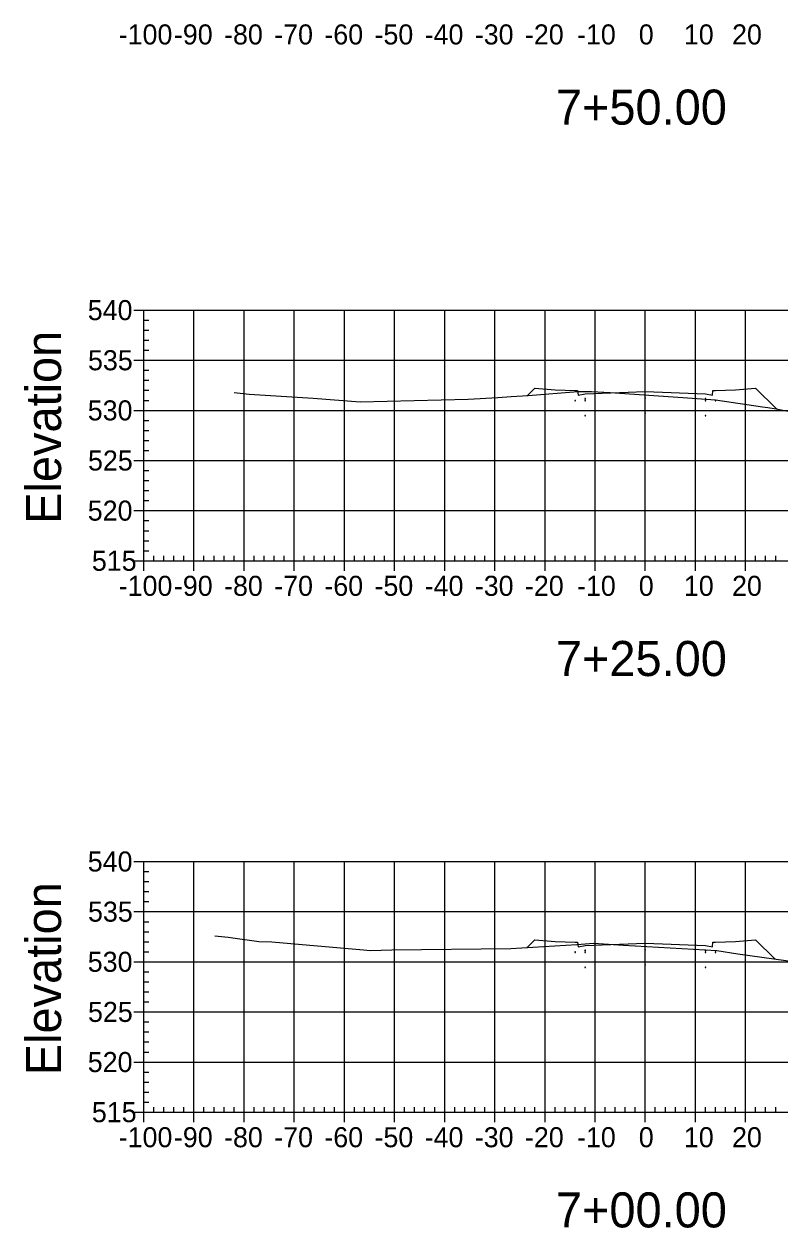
# Model space of a CAD drawing. Extents: x 708103 to 717568, y 374476 to 378707.
# Drawn here: x 716232.6 to 716383.3, y 376985 to 377225.1 of the extents above; entities that cross this region are included whole.
import ezdxf

# ---------------------------------------------------------------- set-up
doc = ezdxf.new("R2010")
doc.units = 0
for name, color, linetype in [('1', 7, 'Continuous'), ('14', 7, 'Continuous'), ('22', 7, 'Continuous'), ('57', 7, 'Continuous'), ('60', 7, 'Continuous'), ('Existing', 7, 'Continuous')]:
    doc.layers.add(name, color=color, linetype=linetype)

msp = doc.modelspace()

# ---------------------------------------------------------------- linework, layer by layer
for points in [[(716356.45, 377150.45), (716356.55, 377150.45), (716356.55, 377150.55), (716356.45, 377150.55)], [(716342.45, 377149.97), (716342.55, 377149.97), (716342.55, 377150.07), (716342.45, 377150.07)], [(716344.45, 377150.31), (716344.55, 377150.31), (716344.55, 377150.41), (716344.45, 377150.41)], [(716344.45, 377149.97), (716344.55, 377149.97), (716344.55, 377150.07), (716344.45, 377150.07)], [(716368.45, 377150.31), (716368.55, 377150.31), (716368.55, 377150.41), (716368.45, 377150.41)], [(716368.45, 377149.97), (716368.55, 377149.97), (716368.55, 377150.07), (716368.45, 377150.07)], [(716370.45, 377149.97), (716370.55, 377149.97), (716370.55, 377150.07), (716370.45, 377150.07)], [(716344.45, 377146.97), (716344.55, 377146.97), (716344.55, 377147.07), (716344.45, 377147.07)], [(716356.45, 377147.45), (716356.55, 377147.45), (716356.55, 377147.55), (716356.45, 377147.55)], [(716368.45, 377146.97), (716368.55, 377146.97), (716368.55, 377147.07), (716368.45, 377147.07)], [(716342.45, 377039.92), (716342.55, 377039.92), (716342.55, 377040.02), (716342.45, 377040.02)], [(716344.45, 377040.26), (716344.55, 377040.26), (716344.55, 377040.36), (716344.45, 377040.36)], [(716344.45, 377039.92), (716344.55, 377039.92), (716344.55, 377040.02), (716344.45, 377040.02)], [(716356.45, 377040.4), (716356.55, 377040.4), (716356.55, 377040.5), (716356.45, 377040.5)], [(716368.45, 377040.26), (716368.55, 377040.26), (716368.55, 377040.36), (716368.45, 377040.36)], [(716368.45, 377039.92), (716368.55, 377039.92), (716368.55, 377040.02), (716368.45, 377040.02)], [(716370.45, 377039.92), (716370.55, 377039.92), (716370.55, 377040.02), (716370.45, 377040.02)], [(716344.45, 377036.92), (716344.55, 377036.92), (716344.55, 377037.02), (716344.45, 377037.02)], [(716356.45, 377037.4), (716356.55, 377037.4), (716356.55, 377037.5), (716356.45, 377037.5)], [(716368.45, 377036.92), (716368.55, 377036.92), (716368.55, 377037.02), (716368.45, 377037.02)]]:
    msp.add_lwpolyline(points, close=True)
at = {"layer": '14'}
for points in [[(716333.03, 377151.03), (716333.03, 377151.08), (716333.03, 377151.03), (716332.98, 377151.03), (716333.03, 377151.03), (716333.03, 377150.98), (716333.03, 377151.03), (716333.08, 377151.03)], [(716382.63, 377148.37), (716382.63, 377148.42), (716382.63, 377148.37), (716382.58, 377148.37), (716382.63, 377148.37), (716382.63, 377148.32), (716382.63, 377148.37), (716382.68, 377148.37)], [(716332.95, 377040.9), (716332.95, 377040.95), (716332.95, 377040.9), (716332.9, 377040.9), (716332.95, 377040.9), (716332.95, 377040.85), (716332.95, 377040.9), (716333, 377040.9)], [(716382.31, 377038.64), (716382.31, 377038.69), (716382.31, 377038.64), (716382.26, 377038.64), (716382.31, 377038.64), (716382.31, 377038.59), (716382.31, 377038.64), (716382.36, 377038.64)]]:
    msp.add_lwpolyline(points, dxfattribs=at)
at = {"layer": '22'}
for points in [[(716333.03, 377151.03), (716334.5, 377152.5), (716338.5, 377152.18), (716342.5, 377152.02), (716343, 377152.02), (716343.08, 377151.11), (716344.5, 377151.36), (716356.5, 377151.84), (716368.5, 377151.36), (716369.91, 377151.11), (716370, 377152.02), (716370.5, 377152.02), (716374.5, 377152.18), (716378.5, 377152.5), (716382.63, 377148.37)], [(716332.95, 377040.9), (716334.5, 377042.45), (716338.5, 377042.13), (716342.5, 377041.97), (716343, 377041.97), (716343.08, 377041.06), (716344.5, 377041.31), (716356.5, 377041.79), (716368.5, 377041.31), (716369.91, 377041.06), (716370, 377041.97), (716370.5, 377041.97), (716374.5, 377042.13), (716378.5, 377042.45), (716382.31, 377038.64)]]:
    msp.add_lwpolyline(points, dxfattribs=at)
at = {"layer": '57'}
for p, q in [((716254.5, 377168.07), (716256.5, 377168.07)), ((716256.5, 377168.07), (716456.5, 377168.07)), ((716256.5, 377118.07), (716256.5, 377168.07)), ((716256.5, 377118.07), (716256.5, 377168.07)), ((716266.5, 377118.07), (716266.5, 377168.07)), ((716276.5, 377118.07), (716276.5, 377168.07)), ((716286.5, 377118.07), (716286.5, 377168.07)), ((716296.5, 377118.07), (716296.5, 377168.07)), ((716306.5, 377118.07), (716306.5, 377168.07)), ((716316.5, 377118.07), (716316.5, 377168.07)), ((716326.5, 377118.07), (716326.5, 377168.07)), ((716336.5, 377118.07), (716336.5, 377168.07)), ((716346.5, 377118.07), (716346.5, 377168.07)), ((716356.5, 377118.07), (716356.5, 377168.07)), ((716366.5, 377118.07), (716366.5, 377168.07)), ((716376.5, 377118.07), (716376.5, 377168.07)), ((716256.5, 377166.07), (716257.5, 377166.07)), ((716256.5, 377164.07), (716257.5, 377164.07)), ((716256.5, 377162.07), (716257.5, 377162.07)), ((716256.5, 377160.07), (716257.5, 377160.07)), ((716254.5, 377158.07), (716256.5, 377158.07)), ((716256.5, 377158.07), (716456.5, 377158.07)), ((716256.5, 377156.07), (716257.5, 377156.07)), ((716256.5, 377154.07), (716257.5, 377154.07)), ((716256.5, 377152.07), (716257.5, 377152.07)), ((716254.5, 377148.07), (716256.5, 377148.07)), ((716256.5, 377150.07), (716257.5, 377150.07)), ((716256.5, 377148.07), (716456.5, 377148.07)), ((716256.5, 377146.07), (716257.5, 377146.07)), ((716256.5, 377144.07), (716257.5, 377144.07)), ((716256.5, 377142.07), (716257.5, 377142.07)), ((716256.5, 377140.07), (716257.5, 377140.07)), ((716254.5, 377138.07), (716256.5, 377138.07)), ((716256.5, 377138.07), (716456.5, 377138.07)), ((716256.5, 377136.07), (716257.5, 377136.07)), ((716256.5, 377134.07), (716257.5, 377134.07)), ((716256.5, 377132.07), (716257.5, 377132.07)), ((716256.5, 377130.07), (716257.5, 377130.07)), ((716254.5, 377128.07), (716256.5, 377128.07)), ((716256.5, 377128.07), (716456.5, 377128.07)), ((716256.5, 377126.07), (716257.5, 377126.07)), ((716256.5, 377124.07), (716257.5, 377124.07)), ((716256.5, 377122.07), (716257.5, 377122.07)), ((716256.5, 377120.07), (716257.5, 377120.07)), ((716254.5, 377118.07), (716256.5, 377118.07)), ((716256.5, 377118.07), (716456.5, 377118.07)), ((716256.5, 377118.07), (716456.5, 377118.07)), ((716256.5, 377116.07), (716256.5, 377118.07)), ((716258.5, 377118.07), (716258.5, 377119.07)), ((716260.5, 377118.07), (716260.5, 377119.07)), ((716262.5, 377118.07), (716262.5, 377119.07)), ((716264.5, 377118.07), (716264.5, 377119.07)), ((716266.5, 377116.07), (716266.5, 377118.07)), ((716268.5, 377118.07), (716268.5, 377119.07)), ((716270.5, 377118.07), (716270.5, 377119.07)), ((716272.5, 377118.07), (716272.5, 377119.07)), ((716274.5, 377118.07), (716274.5, 377119.07)), ((716276.5, 377116.07), (716276.5, 377118.07)), ((716278.5, 377118.07), (716278.5, 377119.07)), ((716280.5, 377118.07), (716280.5, 377119.07)), ((716282.5, 377118.07), (716282.5, 377119.07)), ((716284.5, 377118.07), (716284.5, 377119.07)), ((716286.5, 377116.07), (716286.5, 377118.07)), ((716288.5, 377118.07), (716288.5, 377119.07)), ((716290.5, 377118.07), (716290.5, 377119.07)), ((716292.5, 377118.07), (716292.5, 377119.07)), ((716294.5, 377118.07), (716294.5, 377119.07)), ((716296.5, 377116.07), (716296.5, 377118.07)), ((716298.5, 377118.07), (716298.5, 377119.07)), ((716300.5, 377118.07), (716300.5, 377119.07)), ((716302.5, 377118.07), (716302.5, 377119.07)), ((716304.5, 377118.07), (716304.5, 377119.07)), ((716306.5, 377116.07), (716306.5, 377118.07)), ((716308.5, 377118.07), (716308.5, 377119.07)), ((716310.5, 377118.07), (716310.5, 377119.07)), ((716312.5, 377118.07), (716312.5, 377119.07)), ((716314.5, 377118.07), (716314.5, 377119.07)), ((716316.5, 377116.07), (716316.5, 377118.07)), ((716318.5, 377118.07), (716318.5, 377119.07)), ((716320.5, 377118.07), (716320.5, 377119.07)), ((716322.5, 377118.07), (716322.5, 377119.07)), ((716324.5, 377118.07), (716324.5, 377119.07)), ((716326.5, 377116.07), (716326.5, 377118.07)), ((716328.5, 377118.07), (716328.5, 377119.07)), ((716330.5, 377118.07), (716330.5, 377119.07)), ((716332.5, 377118.07), (716332.5, 377119.07)), ((716334.5, 377118.07), (716334.5, 377119.07)), ((716336.5, 377116.07), (716336.5, 377118.07)), ((716338.5, 377118.07), (716338.5, 377119.07)), ((716340.5, 377118.07), (716340.5, 377119.07)), ((716342.5, 377118.07), (716342.5, 377119.07)), ((716344.5, 377118.07), (716344.5, 377119.07)), ((716346.5, 377116.07), (716346.5, 377118.07)), ((716348.5, 377118.07), (716348.5, 377119.07)), ((716350.5, 377118.07), (716350.5, 377119.07)), ((716352.5, 377118.07), (716352.5, 377119.07)), ((716354.5, 377118.07), (716354.5, 377119.07)), ((716356.5, 377116.07), (716356.5, 377118.07)), ((716358.5, 377118.07), (716358.5, 377119.07)), ((716360.5, 377118.07), (716360.5, 377119.07)), ((716362.5, 377118.07), (716362.5, 377119.07)), ((716364.5, 377118.07), (716364.5, 377119.07)), ((716366.5, 377116.07), (716366.5, 377118.07)), ((716368.5, 377118.07), (716368.5, 377119.07)), ((716370.5, 377118.07), (716370.5, 377119.07)), ((716372.5, 377118.07), (716372.5, 377119.07)), ((716374.5, 377118.07), (716374.5, 377119.07)), ((716376.5, 377116.07), (716376.5, 377118.07)), ((716378.5, 377118.07), (716378.5, 377119.07)), ((716380.5, 377118.07), (716380.5, 377119.07)), ((716382.5, 377118.07), (716382.5, 377119.07)), ((716254.5, 377058.07), (716256.5, 377058.07)), ((716256.5, 377058.07), (716456.5, 377058.07)), ((716256.5, 377008.07), (716256.5, 377058.07)), ((716256.5, 377008.07), (716256.5, 377058.07)), ((716266.5, 377008.07), (716266.5, 377058.07)), ((716276.5, 377008.07), (716276.5, 377058.07)), ((716286.5, 377008.07), (716286.5, 377058.07)), ((716296.5, 377008.07), (716296.5, 377058.07)), ((716306.5, 377008.07), (716306.5, 377058.07)), ((716316.5, 377008.07), (716316.5, 377058.07)), ((716326.5, 377008.07), (716326.5, 377058.07)), ((716336.5, 377008.07), (716336.5, 377058.07)), ((716346.5, 377008.07), (716346.5, 377058.07)), ((716356.5, 377008.07), (716356.5, 377058.07)), ((716366.5, 377008.07), (716366.5, 377058.07)), ((716376.5, 377008.07), (716376.5, 377058.07)), ((716256.5, 377056.07), (716257.5, 377056.07)), ((716256.5, 377054.07), (716257.5, 377054.07)), ((716256.5, 377052.07), (716257.5, 377052.07)), ((716256.5, 377050.07), (716257.5, 377050.07)), ((716254.5, 377048.07), (716256.5, 377048.07)), ((716256.5, 377048.07), (716456.5, 377048.07)), ((716256.5, 377046.07), (716257.5, 377046.07)), ((716256.5, 377044.07), (716257.5, 377044.07)), ((716256.5, 377042.07), (716257.5, 377042.07)), ((716256.5, 377040.07), (716257.5, 377040.07)), ((716254.5, 377038.07), (716256.5, 377038.07)), ((716256.5, 377038.07), (716456.5, 377038.07)), ((716256.5, 377036.07), (716257.5, 377036.07)), ((716256.5, 377034.07), (716257.5, 377034.07)), ((716256.5, 377032.07), (716257.5, 377032.07)), ((716254.5, 377028.07), (716256.5, 377028.07)), ((716256.5, 377030.07), (716257.5, 377030.07)), ((716256.5, 377028.07), (716456.5, 377028.07)), ((716256.5, 377026.07), (716257.5, 377026.07)), ((716256.5, 377024.07), (716257.5, 377024.07)), ((716256.5, 377022.07), (716257.5, 377022.07)), ((716256.5, 377020.07), (716257.5, 377020.07)), ((716254.5, 377018.07), (716256.5, 377018.07)), ((716256.5, 377018.07), (716456.5, 377018.07)), ((716256.5, 377016.07), (716257.5, 377016.07)), ((716256.5, 377014.07), (716257.5, 377014.07)), ((716256.5, 377012.07), (716257.5, 377012.07)), ((716256.5, 377010.07), (716257.5, 377010.07)), ((716258.5, 377008.07), (716258.5, 377009.07)), ((716260.5, 377008.07), (716260.5, 377009.07)), ((716262.5, 377008.07), (716262.5, 377009.07)), ((716264.5, 377008.07), (716264.5, 377009.07)), ((716268.5, 377008.07), (716268.5, 377009.07)), ((716270.5, 377008.07), (716270.5, 377009.07)), ((716272.5, 377008.07), (716272.5, 377009.07)), ((716274.5, 377008.07), (716274.5, 377009.07)), ((716278.5, 377008.07), (716278.5, 377009.07)), ((716280.5, 377008.07), (716280.5, 377009.07)), ((716282.5, 377008.07), (716282.5, 377009.07)), ((716284.5, 377008.07), (716284.5, 377009.07)), ((716288.5, 377008.07), (716288.5, 377009.07)), ((716290.5, 377008.07), (716290.5, 377009.07)), ((716292.5, 377008.07), (716292.5, 377009.07)), ((716294.5, 377008.07), (716294.5, 377009.07)), ((716298.5, 377008.07), (716298.5, 377009.07)), ((716300.5, 377008.07), (716300.5, 377009.07)), ((716302.5, 377008.07), (716302.5, 377009.07)), ((716304.5, 377008.07), (716304.5, 377009.07)), ((716308.5, 377008.07), (716308.5, 377009.07)), ((716310.5, 377008.07), (716310.5, 377009.07)), ((716312.5, 377008.07), (716312.5, 377009.07)), ((716314.5, 377008.07), (716314.5, 377009.07)), ((716318.5, 377008.07), (716318.5, 377009.07)), ((716320.5, 377008.07), (716320.5, 377009.07)), ((716322.5, 377008.07), (716322.5, 377009.07)), ((716324.5, 377008.07), (716324.5, 377009.07)), ((716328.5, 377008.07), (716328.5, 377009.07)), ((716330.5, 377008.07), (716330.5, 377009.07)), ((716332.5, 377008.07), (716332.5, 377009.07)), ((716334.5, 377008.07), (716334.5, 377009.07)), ((716338.5, 377008.07), (716338.5, 377009.07)), ((716340.5, 377008.07), (716340.5, 377009.07)), ((716342.5, 377008.07), (716342.5, 377009.07)), ((716344.5, 377008.07), (716344.5, 377009.07)), ((716348.5, 377008.07), (716348.5, 377009.07)), ((716350.5, 377008.07), (716350.5, 377009.07)), ((716352.5, 377008.07), (716352.5, 377009.07)), ((716354.5, 377008.07), (716354.5, 377009.07)), ((716358.5, 377008.07), (716358.5, 377009.07)), ((716360.5, 377008.07), (716360.5, 377009.07)), ((716362.5, 377008.07), (716362.5, 377009.07)), ((716364.5, 377008.07), (716364.5, 377009.07)), ((716368.5, 377008.07), (716368.5, 377009.07)), ((716370.5, 377008.07), (716370.5, 377009.07)), ((716372.5, 377008.07), (716372.5, 377009.07)), ((716374.5, 377008.07), (716374.5, 377009.07)), ((716378.5, 377008.07), (716378.5, 377009.07)), ((716380.5, 377008.07), (716380.5, 377009.07)), ((716382.5, 377008.07), (716382.5, 377009.07)), ((716254.5, 377008.07), (716256.5, 377008.07)), ((716256.5, 377008.07), (716456.5, 377008.07)), ((716256.5, 377008.07), (716456.5, 377008.07)), ((716256.5, 377006.07), (716256.5, 377008.07)), ((716266.5, 377006.07), (716266.5, 377008.07)), ((716276.5, 377006.07), (716276.5, 377008.07)), ((716286.5, 377006.07), (716286.5, 377008.07)), ((716296.5, 377006.07), (716296.5, 377008.07)), ((716306.5, 377006.07), (716306.5, 377008.07)), ((716316.5, 377006.07), (716316.5, 377008.07)), ((716326.5, 377006.07), (716326.5, 377008.07)), ((716336.5, 377006.07), (716336.5, 377008.07)), ((716346.5, 377006.07), (716346.5, 377008.07)), ((716356.5, 377006.07), (716356.5, 377008.07)), ((716366.5, 377006.07), (716366.5, 377008.07)), ((716376.5, 377006.07), (716376.5, 377008.07))]:
    msp.add_line(p, q, dxfattribs=at)
at = {"layer": 'Existing'}
for points in [[(716274.52, 377151.66), (716277.48, 377151.33), (716290.26, 377150.52), (716299.65, 377149.8), (716321.2, 377150.29), (716327.11, 377150.66), (716329.74, 377150.83), (716333.13, 377151.04), (716343.04, 377151.81), (716345.78, 377151.83), (716349.49, 377151.63), (716363.98, 377150.61), (716370.49, 377150.16), (716379.9, 377148.78), (716380.95, 377148.63), (716382.59, 377148.38), (716395.52, 377145.83), (716396.57, 377145.66), (716412.58, 377146.07), (716413.18, 377146.08), (716413.29, 377146.08), (716413.31, 377146.08), (716435.18, 377144.33)], [(716270.64, 377043.27), (716273.29, 377042.97), (716279.44, 377042.13), (716282.06, 377042.04), (716292.63, 377041.15), (716299.55, 377040.52), (716301.67, 377040.31), (716305.93, 377040.42), (716329.66, 377040.69), (716342.83, 377041.54), (716345.36, 377041.74), (716346.09, 377041.76), (716347.18, 377041.69), (716352.12, 377041.41), (716370.77, 377040.31), (716374.92, 377039.66), (716394.53, 377036.95), (716398.36, 377036.39), (716400.73, 377036.01), (716405.42, 377035.58), (716411.26, 377035.83), (716415.54, 377035.59), (716430.98, 377034.36)]]:
    msp.add_lwpolyline(points, dxfattribs=at)

# ---------------------------------------------------------------- texts
at = {"layer": '1'}
for s, p in [('7+50.00', (716338.67, 377205.07)), ('7+25.00', (716338.67, 377095.07)), ('7+00.00', (716338.67, 376985.07))]:
    msp.add_text(s, height=7, dxfattribs=at).set_placement(p)
at = {"layer": '14'}
for p in [(716338.46, 377152.13), (716338.46, 377151.47), (716342.46, 377151.31), (716370.46, 377151.31), (716374.46, 377152.13), (716374.46, 377151.47), (716338.46, 377042.08), (716338.46, 377041.42), (716342.46, 377041.26), (716370.46, 377041.26), (716374.46, 377042.08), (716374.46, 377041.42)]:
    msp.add_text('+', height=0.1, dxfattribs=at).set_placement(p)
at = {"layer": '57'}
for s, p in [('-100', (716251.49, 377221.07)), ('-90', (716262.5, 377221.07)), ('-80', (716272.5, 377221.07)), ('-70', (716282.5, 377221.07)), ('-60', (716292.5, 377221.07)), ('-50', (716302.5, 377221.07)), ('-40', (716312.5, 377221.07)), ('-30', (716322.5, 377221.07)), ('-20', (716332.5, 377221.07)), ('-10', (716342.88, 377221.07)), ('0', (716355.2, 377221.07)), ('10', (716364.19, 377221.07)), ('20', (716373.8, 377221.07)), ('540', (716245.32, 377166.07)), ('535', (716245.37, 377156.07)), ('530', (716245.32, 377146.07)), ('525', (716245.37, 377136.07)), ('520', (716245.32, 377126.07)), ('515', (716246.14, 377116.07)), ('-100', (716251.49, 377111.07)), ('-90', (716262.5, 377111.07)), ('-80', (716272.5, 377111.07)), ('-70', (716282.5, 377111.07)), ('-60', (716292.5, 377111.07)), ('-50', (716302.5, 377111.07)), ('-40', (716312.5, 377111.07)), ('-30', (716322.5, 377111.07)), ('-20', (716332.5, 377111.07)), ('-10', (716342.88, 377111.07)), ('0', (716355.2, 377111.07)), ('10', (716364.19, 377111.07)), ('20', (716373.8, 377111.07)), ('540', (716245.32, 377056.07)), ('535', (716245.37, 377046.07)), ('530', (716245.32, 377036.07)), ('525', (716245.37, 377026.07)), ('520', (716245.32, 377016.07)), ('515', (716246.14, 377006.07)), ('-100', (716251.49, 377001.07)), ('-90', (716262.5, 377001.07)), ('-80', (716272.5, 377001.07)), ('-70', (716282.5, 377001.07)), ('-60', (716292.5, 377001.07)), ('-50', (716302.5, 377001.07)), ('-40', (716312.5, 377001.07)), ('-30', (716322.5, 377001.07)), ('-20', (716332.5, 377001.07)), ('-10', (716342.88, 377001.07)), ('0', (716355.2, 377001.07)), ('10', (716364.19, 377001.07)), ('20', (716373.8, 377001.07))]:
    msp.add_text(s, height=4, dxfattribs=at).set_placement(p)
at = {"layer": '60'}
for p in [(716240, 377125.44), (716240, 377015.44)]:
    msp.add_text('Elevation', height=7, rotation=90, dxfattribs=at).set_placement(p)

doc.saveas('drawing.dxf')
